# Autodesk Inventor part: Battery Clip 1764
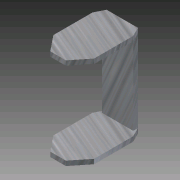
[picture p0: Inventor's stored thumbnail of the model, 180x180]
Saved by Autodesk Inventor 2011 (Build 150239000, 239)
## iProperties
Created: 2008-01
Part Number: Battery Clip 1764
Document SubType Name: Modeling
Designer: rlindsay
Density: 1 g/cm^3
Author: rlindsay
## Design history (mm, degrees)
sketch "Sketch1"
  geometry: L1 (-24.151, -9.08)-(-19.071, -9.08); L2 (-19.071, -9.08)-(-19.071, -22.415); L3 (-19.071, -22.415)-(-24.151, -22.415); L4 (-24.151, -22.415)-(-24.151, -9.08)
  constraints: 8 end point, 2 parallel, 1 horizontal, 1 perpendicular
  dimensions: "d0" = 5.08 distance between parallel lines of L2 L4; "d1" = 13.335 distance between parallel lines of L3 L1
extrude "Extrusion1" new body sketch "Sketch1" distance "d2" = 0.762; taper "d3" = 0 deg
sketch "Sketch2"
  geometry: L1 (0, -0.762)-(5.08, -0.762) reference; L2 (5.08, 0)-(5.08, -0.762) reference; L3 (0, 0)-(5.08, 0) reference; L4 (0, 0)-(0, -0.762) reference; L5 (0, 0)-(-0.762, -1.524); L6 (-0.762, -1.524)-(-0.762, -7.874); L7 (-0.762, -7.874)-(1.27, -10.414); L8 (1.27, -10.414)-(3.81, -10.414); L9 (3.81, -10.414)-(5.842, -7.874); L10 (5.842, -7.874)-(5.842, -1.524); L11 (5.842, -1.524)-(5.08, 0)
  constraints: 14 end point, 1 parallel, 1 perpendicular, 1 vertical
  dimensions: "d4" = 6.604 distance between parallel lines of L10 L6; "d5" = 2.54 distance of L7.end L8.end; "d6" = 2.54 distance from line of L6.end L8; "d7" = 2.032 distance from line of L6 L7.end; "d8" = 6.35 distance of L5.end L6.end; "d9" = 2.54 distance from line of L8 L9.end; "d10" = 10.414 distance between parallel lines of L8 L3; "d11" = 0.762 distance between parallel lines of L4 L6; "d12" = 0.762 distance between parallel lines of L2 L10 (derived); "d13" = 6.35 distance of L9.end L10.end
extrude "Extrusion2" join sketch "Sketch2" distance "d14" = 0.762; taper "d15" = 0 deg
workplane "Work Plane2"
mirror "Mirror1"
body "Solid1"
other parameters: "d17" = -6.6675
